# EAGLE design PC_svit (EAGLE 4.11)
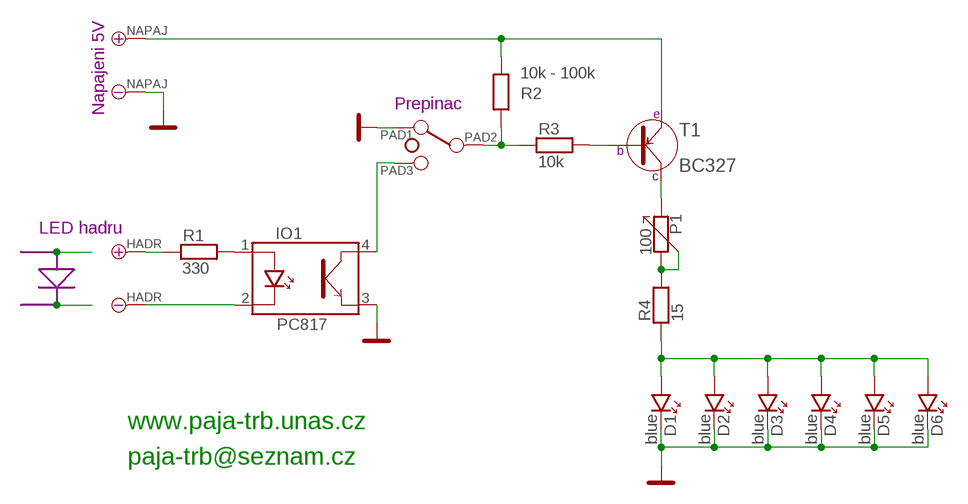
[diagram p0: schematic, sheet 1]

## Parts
D1  blue  LED_5  [LED_5]
D2  blue  LED_5  [LED_5]
D3  blue  LED_5  [LED_5]
D4  blue  LED_5  [LED_5]
D5  blue  LED_5  [LED_5]
D6  blue  LED_5  [LED_5]
HADR  PAD_2+-  [PAD_2+-]
IO1  PC817  [DIL4]
NAPAJ  PAD_2+-  [PAD_2+-]
P1  100  PC16ML  [PC16ML]
PAD1  PAD_1  [PAD_1]
PAD2  PAD_1  [PAD_1]
PAD3  PAD_1  [PAD_1]
R1  330  R_7,5  [R-7,5]
R2  10k - 100k  R_7,5  [R-7,5]
R3  10k  R_7,5  [R-7,5]
R4  15  R_7,5  [R-7,5]
T1  BC327  [TO-92]

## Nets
GND: D1.K D2.K D3.K D4.K D5.K D6.K IO1.3(E) NAPAJ.- PAD1.1
N$1: HADR.+ R1.1
N$2: IO1.1(A) R1.2
N$3: HADR.- IO1.2(K)
N$4: P1.1 P1.2 R4.2
N$5: P1.3 T1.1(C)
N$6: D1.A D2.A D3.A D4.A D5.A D6.A R4.1
N$8: R3.2 T1.2(B)
N$9: PAD2.1 R2.1 R3.1
N$10: NAPAJ.+ R2.2 T1.3(E)
N$12: IO1.4(C) PAD3.1

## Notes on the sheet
- Napajeni 5V
- Prepinac
- LED hadru
- www.paja-trb.unas.cz
- paja-trb@seznam.cz

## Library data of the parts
D1-D6 = #PaJa_15:LED: LED - jednobarevna
HADR NAPAJ = #PaJa_15:PAD_2+-: Pajeci bod - 2,54 mm prumer, + a - , napajeci
IO1 = #PaJa_15:PC817: Optoclen
P1 = #PaJa_15:PC16ML: Potenciometr - plastovy - 100R az 5M
PAD1-PAD3 = #PaJa_15:PAD_1: Pajeci bod - 2,54 mm prumer
R1-R4 = #PaJa_15:R: Rezistor
T1 = #PaJa_15:BC327: Tranzistor PNP - Univerzalni NF - Ic=0,5A

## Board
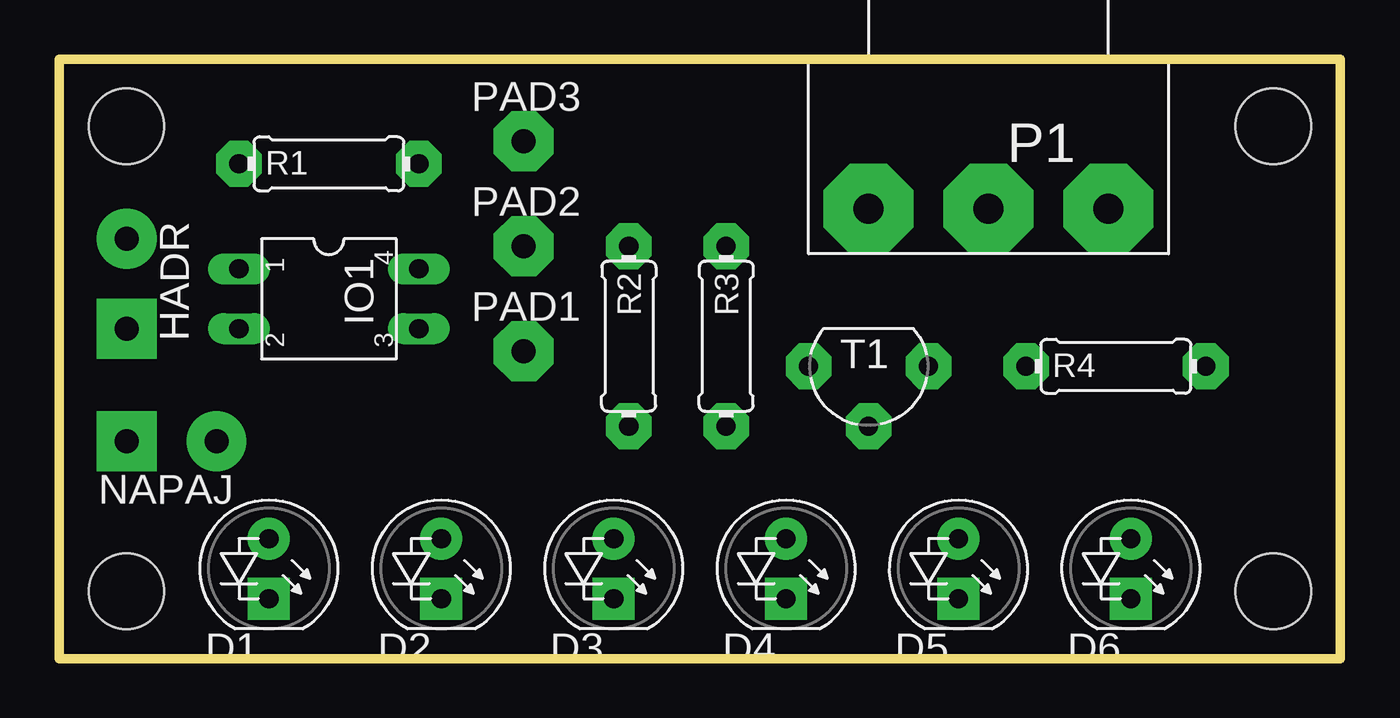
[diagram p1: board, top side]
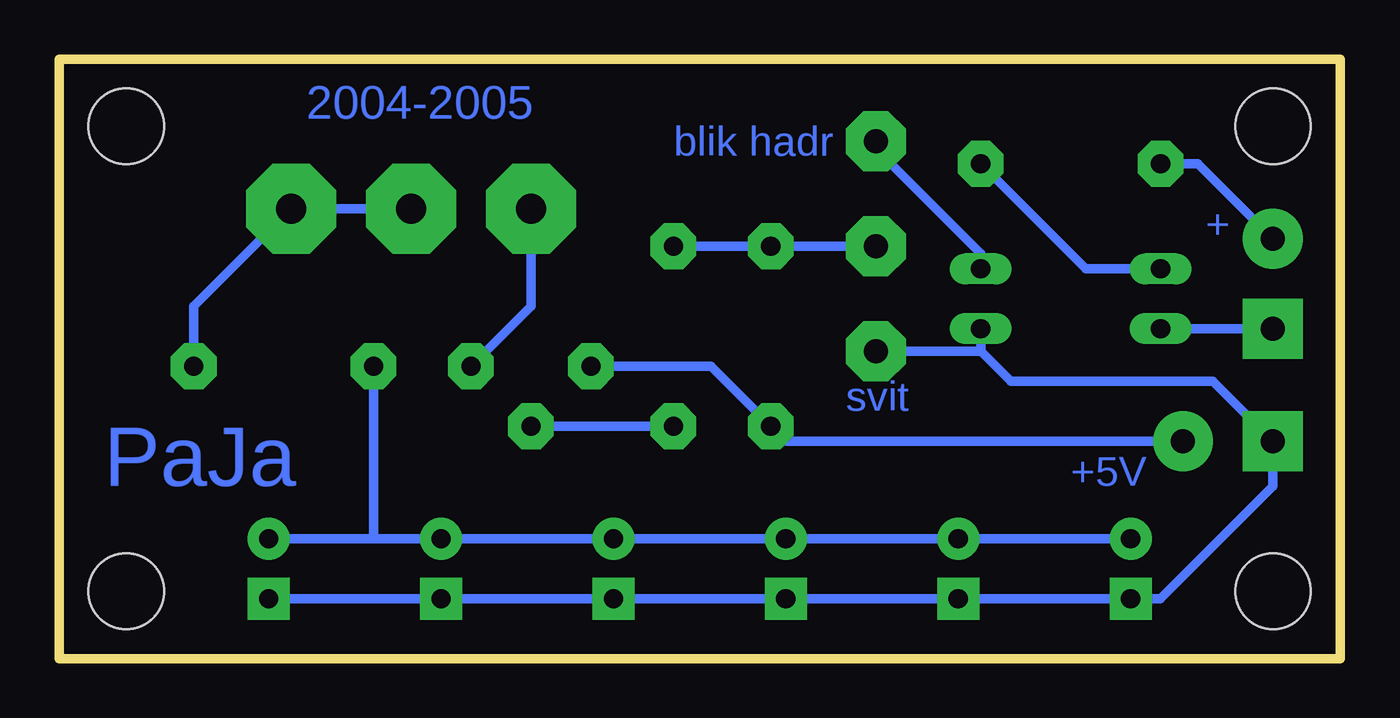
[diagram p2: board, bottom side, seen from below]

Size 54.28 x 25.39 mm. Coordinates in mm from the lower left corner, seen from the top.
Outline: 0,0 54.28,0 54.28,25.39 0,25.39 0,0
Copper layers (1*16): Top 0.035mm / dielectric 1.5mm / Bottom 0.035mm
Design rules "default": minimum track width 10mil, minimum drill 24mil, track to track 8mil, track to pad 8mil, pad to pad 8mil, via to via 8mil, smd to smd 8mil, copper to edge 40mil, drill to drill 8mil, minimum pad ring 10mil, minimum via ring 8mil, stop-mask expansion 4mil, vias tented up to drill 0mil, thermal gap 10mil
Holes 3.2 mm at 2.86,2.86 2.86,22.54 51.44,22.54 51.44,2.86

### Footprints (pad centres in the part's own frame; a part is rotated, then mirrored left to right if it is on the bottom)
LED_5 = drill 0.813 pad 1.778 round: A -1.27,0 | drill 0.813 pad 1.778 square: K 1.27,0
PAD_2+- = drill 1.016 pad 2.54 round: + -1.905,0 | drill 1.016 pad 2.54 square: - 1.905,0
DIL4 = drill 0.813 pad 1.27 long: 1 -1.27,-3.81; 2 1.27,-3.81; 3 1.27,3.81; 4 -1.27,3.81
PC16ML = drill 1.27 pad 3.81 octagon: 1 -5.08,0; 2 0,0; 3 5.08,0
PAD_1 = drill 1.016 pad 2.54 octagon: 1 0,0
R-7,5 = drill 0.813 pad 1.93 octagon: 1 -3.81,0; 2 3.81,0
TO-92 = drill 0.813 pad 1.93 octagon: 1 0,2.54; 2 2.54,0; 3 0,-2.54

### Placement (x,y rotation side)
D1  8.89,3.81 270 top
D2  16.19,3.81 270 top
D3  23.5,3.81 270 top
D4  30.8,3.81 270 top
D5  38.1,3.81 270 top
D6  45.4,3.81 270 top
HADR  2.86,15.88 270 top
IO1  11.43,15.24 270 top
NAPAJ  4.76,9.21 180 top
P1  39.37,19.05 180 top
PAD1  19.68,13.02 0 top
PAD2  19.68,17.46 0 top
PAD3  19.68,21.91 0 top
R1  11.43,20.95 0 top
R2  24.13,13.65 270 top
R3  28.26,13.65 270 top
R4  44.77,12.38 0 top
T1  34.29,12.38 270 top

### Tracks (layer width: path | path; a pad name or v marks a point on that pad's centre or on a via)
GND
  Bottom 0.406: D6.K D5.K D4.K D3.K D2.K D1.K 7.62,2.54 2.86,7.3 NAPAJ.- 5.4,11.75 13.97,11.75 15.24,13.02 | 15.24,13.02 PAD1.1 | 15.24,13.02 IO1.3
N$1
  Bottom 0.406: HADR.+ 6.03,20.95 R1.1
N$2
  Bottom 0.406: IO1.1 10.79,16.51 R1.2
N$3
  Bottom 0.406: HADR.- IO1.2
N$4
  Bottom 0.406: P1.2 P1.1 48.58,14.92 R4.2
N$5
  Bottom 0.406: P1.3 34.29,14.92 T1.1
N$6
  Bottom 0.406: 40.96,5.08 D5.A D4.A D3.A D2.A D1.A | 40.96,5.08 D6.A | 40.96,5.08 R4.1
N$8
  Bottom 0.406: R3.2 T1.2
N$9
  Bottom 0.406: PAD2.1 R2.1 R3.1
N$10
  Bottom 0.406: NAPAJ.+ 23.5,9.21 R2.2 26.67,12.38 T1.3
N$12
  Bottom 0.406: PAD3.1 19.68,21.59 15.24,17.14 IO1.4

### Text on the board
Bottom: 2004-2005 | blik hadr | + | svit | +5V | PaJa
